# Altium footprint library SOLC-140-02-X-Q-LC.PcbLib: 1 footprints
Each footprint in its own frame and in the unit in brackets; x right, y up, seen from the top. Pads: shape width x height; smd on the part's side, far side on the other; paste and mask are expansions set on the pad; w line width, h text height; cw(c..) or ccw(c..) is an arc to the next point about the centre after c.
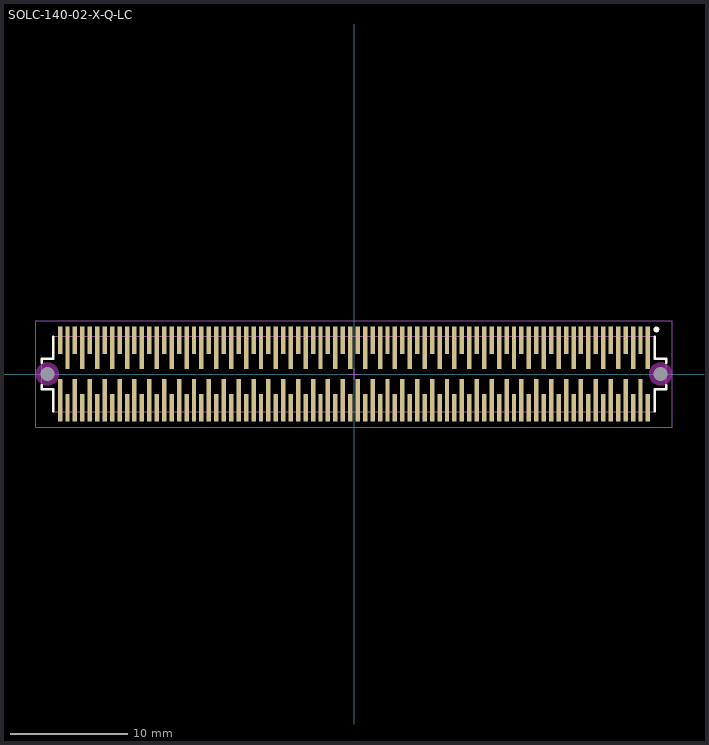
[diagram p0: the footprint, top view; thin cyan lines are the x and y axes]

## SOLC-140-02-X-Q-LC [mm] "1.27mm pitch, 160 pin, socket strip; 4 rows, w/locking clips, SMT"
height 4.62
pads (162):
  round 1 hole 1.2 unplated mask+0: 161(-26.162,0) 162(26.162,0)
  rect 0.38x2.36 smd mask+0: A1(24.447,2.885) A2(23.177,2.885) A3(21.907,2.885) A4(20.637,2.885) A5(19.367,2.885) A6(18.098,2.885) A7(16.828,2.885) A8(15.557,2.885) A9(14.287,2.885) A10(13.018,2.885) A11(11.747,2.885) A12(10.477,2.885) A13(9.207,2.885) A14(7.938,2.885) A15(6.667,2.885) A16(5.397,2.885) A17(4.127,2.885) A18(2.857,2.885) A19(1.587,2.885) A20(0.318,2.885) A21(-0.953,2.885) A22(-2.222,2.885) A23(-3.492,2.885) A24(-4.763,2.885) A25(-6.032,2.885) A26(-7.302,2.885) A27(-8.572,2.885) A28(-9.842,2.885) A29(-11.112,2.885) A30(-12.383,2.885) A31(-13.652,2.885) A32(-14.922,2.885) A33(-16.192,2.885) A34(-17.462,2.885) A35(-18.732,2.885) A36(-20.002,2.885) A37(-21.273,2.885) A38(-22.543,2.885) A39(-23.812,2.885) A40(-25.082,2.885) D1(25.082,-2.885) D2(23.812,-2.885) D3(22.543,-2.885) D4(21.273,-2.885) D5(20.002,-2.885) D6(18.732,-2.885) D7(17.462,-2.885) D8(16.192,-2.885) D9(14.922,-2.885) D10(13.652,-2.885) D11(12.383,-2.885) D12(11.112,-2.885) D13(9.842,-2.885) D14(8.572,-2.885) D15(7.302,-2.885) D16(6.032,-2.885) D17(4.763,-2.885) D18(3.492,-2.885) D19(2.222,-2.885) D20(0.953,-2.885) D21(-0.318,-2.885) D22(-1.587,-2.885) D23(-2.857,-2.885) D24(-4.127,-2.885) D25(-5.397,-2.885) D26(-6.667,-2.885) D27(-7.938,-2.885) D28(-9.207,-2.885) D29(-10.477,-2.885) D30(-11.747,-2.885) D31(-13.018,-2.885) D32(-14.287,-2.885) D33(-15.557,-2.885) D34(-16.828,-2.885) D35(-18.098,-2.885) D36(-19.367,-2.885) D37(-20.637,-2.885) D38(-21.907,-2.885) D39(-23.177,-2.885) D40(-24.447,-2.885)
  rect 0.38x3.63 smd mask+0: B1(25.082,2.25) B2(23.812,2.25) B3(22.543,2.25) B4(21.273,2.25) B5(20.002,2.25) B6(18.732,2.25) B7(17.462,2.25) B8(16.192,2.25) B9(14.922,2.25) B10(13.652,2.25) B11(12.383,2.25) B12(11.112,2.25) B13(9.842,2.25) B14(8.572,2.25) B15(7.302,2.25) B16(6.032,2.25) B17(4.763,2.25) B18(3.492,2.25) B19(2.222,2.25) B20(0.953,2.25) B21(-0.318,2.25) B22(-1.587,2.25) B23(-2.857,2.25) B24(-4.127,2.25) B25(-5.397,2.25) B26(-6.667,2.25) B27(-7.938,2.25) B28(-9.207,2.25) B29(-10.477,2.25) B30(-11.747,2.25) B31(-13.018,2.25) B32(-14.287,2.25) B33(-15.557,2.25) B34(-16.828,2.25) B35(-18.098,2.25) B36(-19.367,2.25) B37(-20.637,2.25) B38(-21.907,2.25) B39(-23.177,2.25) B40(-24.447,2.25) C1(24.447,-2.25) C2(23.177,-2.25) C3(21.907,-2.25) C4(20.637,-2.25) C5(19.367,-2.25) C6(18.098,-2.25) C7(16.828,-2.25) C8(15.557,-2.25) C9(14.287,-2.25) C10(13.018,-2.25) C11(11.747,-2.25) C12(10.477,-2.25) C13(9.207,-2.25) C14(7.938,-2.25) C15(6.667,-2.25) C16(5.397,-2.25) C17(4.127,-2.25) C18(2.857,-2.25) C19(1.587,-2.25) C20(0.318,-2.25) C21(-0.953,-2.25) C22(-2.222,-2.25) C23(-3.492,-2.25) C24(-4.763,-2.25) C25(-6.032,-2.25) C26(-7.302,-2.25) C27(-8.572,-2.25) C28(-9.842,-2.25) C29(-11.112,-2.25) C30(-12.383,-2.25) C31(-13.652,-2.25) C32(-14.922,-2.25) C33(-16.192,-2.25) C34(-17.462,-2.25) C35(-18.732,-2.25) C36(-20.002,-2.25) C37(-21.273,-2.25) C38(-22.543,-2.25) C39(-23.812,-2.25) C40(-25.082,-2.25)
Top Overlay:
  circle w0.25: c25.8,3.8 r0.125
  lines w0.2: -26.65,-0.95 -26.65,-1.3 -25.65,-1.3 -25.65,-3.2 ; -26.65,0.95 -26.65,1.3 -25.65,1.3 -25.65,3.2 ; 25.65,-3.2 25.65,-1.3 26.65,-1.3 26.65,-0.95 ; 25.65,3.2 25.65,1.3 26.65,1.3 26.65,0.95
Keep-Out Layer:
  pour cut-out: 27.145,0 27.112,0.255 27.014,0.492 26.857,0.695 26.654,0.852 26.417,0.95 26.162,0.983 25.907,0.95 25.67,0.852 25.467,0.695 25.31,0.492 25.212,0.255 25.179,0 25.212,-0.255 25.31,-0.492 25.467,-0.695 25.67,-0.852 25.907,-0.95 26.162,-0.983 26.417,-0.95 26.654,-0.852 26.857,-0.695 27.014,-0.492 27.112,-0.255
  pour cut-out: -25.179,0 -25.212,0.255 -25.31,0.492 -25.467,0.695 -25.67,0.852 -25.907,0.95 -26.162,0.983 -26.417,0.95 -26.654,0.852 -26.857,0.695 -27.014,0.492 -27.112,0.255 -27.145,0 -27.112,-0.255 -27.014,-0.492 -26.857,-0.695 -26.654,-0.852 -26.417,-0.95 -26.162,-0.983 -25.907,-0.95 -25.67,-0.852 -25.467,-0.695 -25.31,-0.492 -25.212,-0.255
Mechanical 12:
  lines w0.001: -26.65,-1.3 -26.65,1.3 -25.65,1.3 -25.65,3.2 25.65,3.2 25.65,1.3 26.65,1.3 26.65,-1.3 25.65,-1.3 25.65,-3.2 -25.65,-3.2 -25.65,-1.3 -26.65,-1.3
Mechanical 13:
  lines w0.1: -26.65,-1.3 -26.65,1.3 -25.65,1.3 -25.65,3.2 25.65,3.2 25.65,1.3 26.65,1.3 26.65,-1.3 25.65,-1.3 25.65,-3.2 -25.65,-3.2 -25.65,-1.3 -26.65,-1.3
  text ".Designator" at 0,-0.127 h1.52
Mechanical 15:
  lines w0.05: -0.5,0 0.5,0 ; 0,-0.5 0,0.5 ; -27.15,-4.55 -27.15,4.55 27.15,4.55 27.15,-4.55 -27.15,-4.55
